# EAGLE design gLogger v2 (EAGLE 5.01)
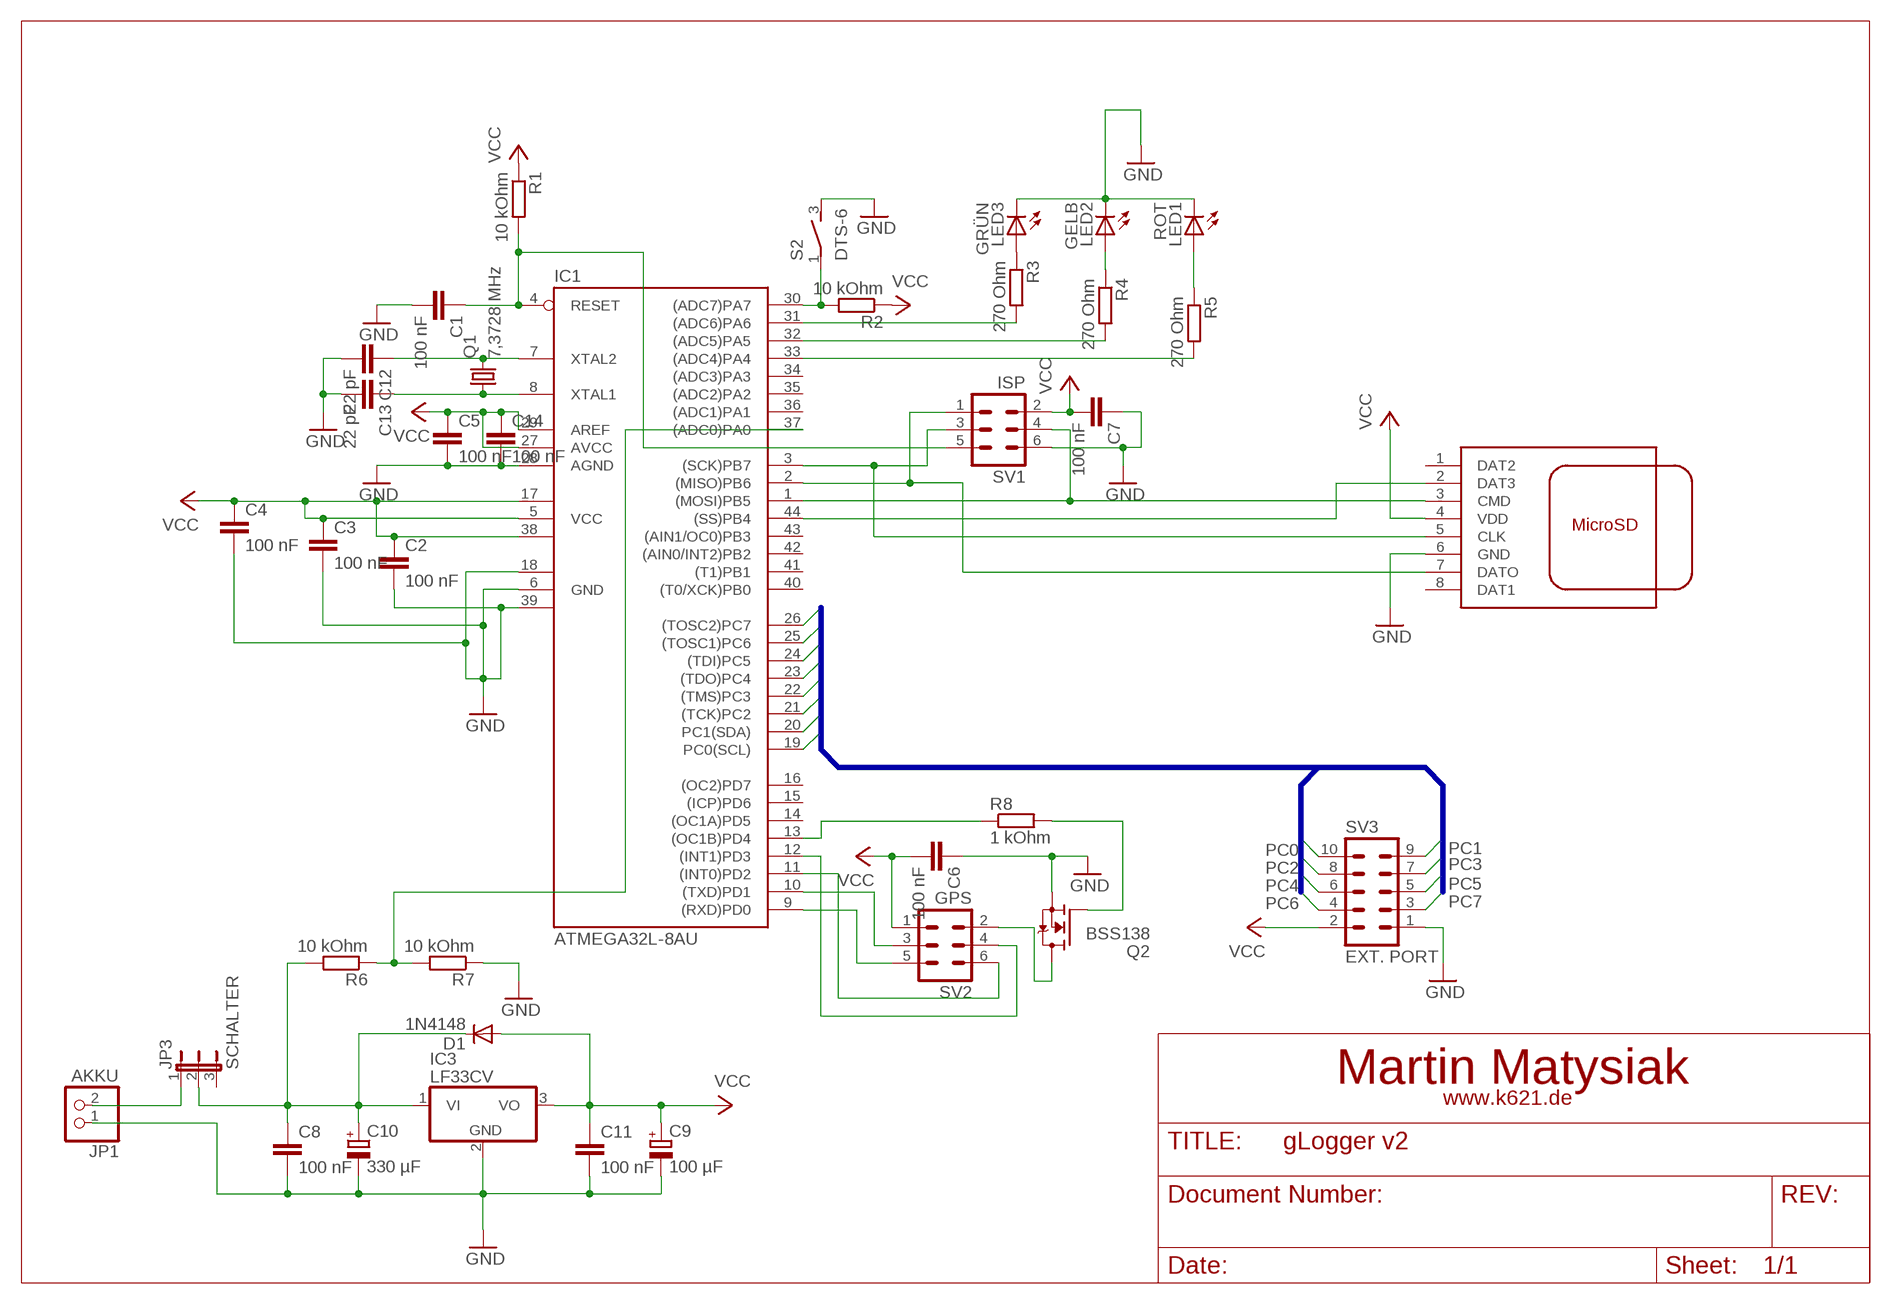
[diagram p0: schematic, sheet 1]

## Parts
C1  100 nF  C-EUC1206  [C1206]
C2  100 nF  C-EUC1206  [C1206]
C3  100 nF  C-EUC1206  [C1206]
C4  100 nF  C-EUC1206  [C1206]
C5  100 nF  C-EUC1206  [C1206]
C6  100 nF  C-EUC1206  [C1206]
C7  100 nF  C-EUC1206  [C1206]
C8  100 nF  C-EUC1206  [C1206]
C9  100 µF  CPOL-EUE2-5  [E2-5]
C10  330 µF  CPOL-EUE2-5  [E2-5]
C11  100 nF  C-EUC1206  [C1206]
C12  22 pF  C-EUC1206  [C1206]
C13  22 pF  C-EUC1206  [C1206]
C14  100 nF  C-EUC1206  [C1206]
D1  1N4148  [DO35-10]
IC1  ATMEGA32L-8AU  MEGA32-A  [TQFP44]
IC2  SCHA2B300  [SCHA2B300]
IC3  LF33CV  [TO220H]
JP1  AKKU  PINHD-1X2  [1X02]
JP3  SCHALTER  JP2E  [JP2]
LED1  ROT  LED3MM  [LED3MM]
LED2  GELB  LED3MM  [LED3MM]
LED3  GRÜN  LED3MM  [LED3MM]
Q1  7,3728 MHz  CRYSTALSM49  [SM49]
Q2  BSS138  [SOT23]
R1  10 kOhm  R-EU_R1206  [R1206]
R2  10 kOhm  R-EU_R1206  [R1206]
R3  270 Ohm  R-EU_R1206  [R1206]
R4  270 Ohm  R-EU_R1206  [R1206]
R5  270 Ohm  R-EU_R1206  [R1206]
R6  10 kOhm  R-EU_R1206  [R1206]
R7  10 kOhm  R-EU_R1206  [R1206]
R8  1 kOhm  R-EU_0207/5V  [0207/5V]
S2  DTS-6  [DTS-6]
SV1  ISP  MA03-2  [MA03-2]
SV2  GPS  MA03-2  [MA03-2]
SV3  EXT. PORT  MA05-2  [MA05-2]

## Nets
GND: C1.2 C2.2 C3.2 C4.2 C5.2 C6.1 C7.1 C8.2 C9.- C10.- C11.2 C12.2 C13.2 C14.2 IC1.6(GND) IC1.18(GND1) IC1.28(AGND) IC1.39(GND2) IC2.6(GND) IC3.2(GND) JP1.1 LED1.K(C) LED2.K(C) LED3.K(C) Q2.2(S) R7.1 S2.3(S) SV1.6 SV3.1
N$1: C1.1 IC1.4(RESET) R1.2 SV1.5
N$2: IC1.3((SCK)PB7) IC2.5(CLK) SV1.3
N$3: IC1.11((INT0)PD2) SV2.6
N$4: IC1.12((INT1)PD3) SV2.4
N$5: C13.1 IC1.8(XTAL1) Q1.1
N$6: LED1.A R5.1
N$7: LED2.A R4.1
N$8: LED3.A R3.1
N$9: IC1.30((ADC7)PA7) R2.2 S2.1(P)
N$10: IC1.31((ADC6)PA6) R3.2
N$11: IC1.32((ADC5)PA5) R4.2
N$12: IC1.33((ADC4)PA4) R5.2
N$14: JP1.2 JP3.1
N$15: C12.1 IC1.7(XTAL2) Q1.2
N$16: Q2.3(D) SV2.2
N$17: Q2.1(G) R8.2
N$18: C8.1 C10.+ D1.C IC3.1(VI) JP3.2 R6.2
N$19: IC1.37((ADC0)PA0) R6.1 R7.2
N$20: IC1.13((OC1B)PD4) R8.1
N$23: IC1.9((RXD)PD0) SV2.5
N$24: IC1.10((TXD)PD1) SV2.3
N$25: IC1.2((MISO)PB6) IC2.7(DATO) SV1.1
N$27: IC1.1((MOSI)PB5) IC2.3(CMD) SV1.4
N$30: IC1.44((SS)PB4) IC2.2(DAT3)
PC0: IC1.19(PC0(SCL)) SV3.10
PC1: IC1.20(PC1(SDA)) SV3.9
PC2: IC1.21((TCK)PC2) SV3.8
PC3: IC1.22((TMS)PC3) SV3.7
PC4: IC1.23((TDO)PC4) SV3.6
PC5: IC1.24((TDI)PC5) SV3.5
PC6: IC1.25((TOSC1)PC6) SV3.4
PC7: IC1.26((TOSC2)PC7) SV3.3
VCC: C2.1 C3.1 C4.1 C5.1 C6.2 C7.2 C9.+ C11.1 C14.1 D1.A IC1.5(VCC) IC1.17(VCC1) IC1.27(AVCC) IC1.29(AREF) IC1.38(VCC2) IC2.4(VDD) IC3.3(VO) R1.1 R2.1 SV1.2 SV2.1 SV3.2
Unconnected: IC1.14((OC1A)PD5) IC1.15((ICP)PD6) IC1.16((OC2)PD7) IC1.34((ADC3)PA3) IC1.35((ADC2)PA2) IC1.36((ADC1)PA1) IC1.40((T0/XCK)PB0) IC1.41((T1)PB1) IC1.42((AIN0/INT2)PB2) IC1.43((AIN1/OC0)PB3) IC2.1(DAT2) IC2.8(DAT1) JP3.3

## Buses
EXT.PORT:PC0,PC1,PC2,PC3,PC4,PC5,PC6,PC7

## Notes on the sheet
- Martin Matysiak
- www.k621.de

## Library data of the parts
C1-C8 C11-C14 = rcl:C-EU: CAPACITOR, European symbol
C9 C10 = rcl:CPOL-EU: POLARIZED CAPACITOR, European symbol
D1 = diode:1N4148: DIODE
IC1 = atmel:MEGA32: MICROCONTROLLER 32 Kbytes FLASH 2 Kbytes SRAM 1 Kbytes EEPROM USART 8-channel 10 bit ADC Source: www.atmel.com .. doc2503.pdf
IC2 = selfmade:SCHA2B300: SCHA2B300 Micro SD Slot Available at csd-electronics
IC3 = linear:LF33CV
JP1 = pinhead:PINHD-1X2: PIN HEADER
JP3 = jumper:JP2E: JUMPER
LED1-LED3 = led:LED: LED
Q1 = crystal:CRYSTAL: CRYSTAL
Q2 = transistor-fet:BSS138
R1-R8 = rcl:R-EU_: RESISTOR, European symbol
S2 = switch:DTS-6: DTS-6
SV1 SV2 = con-lstb:MA03-2: PIN HEADER
SV3 = con-lstb:MA05-2: PIN HEADER

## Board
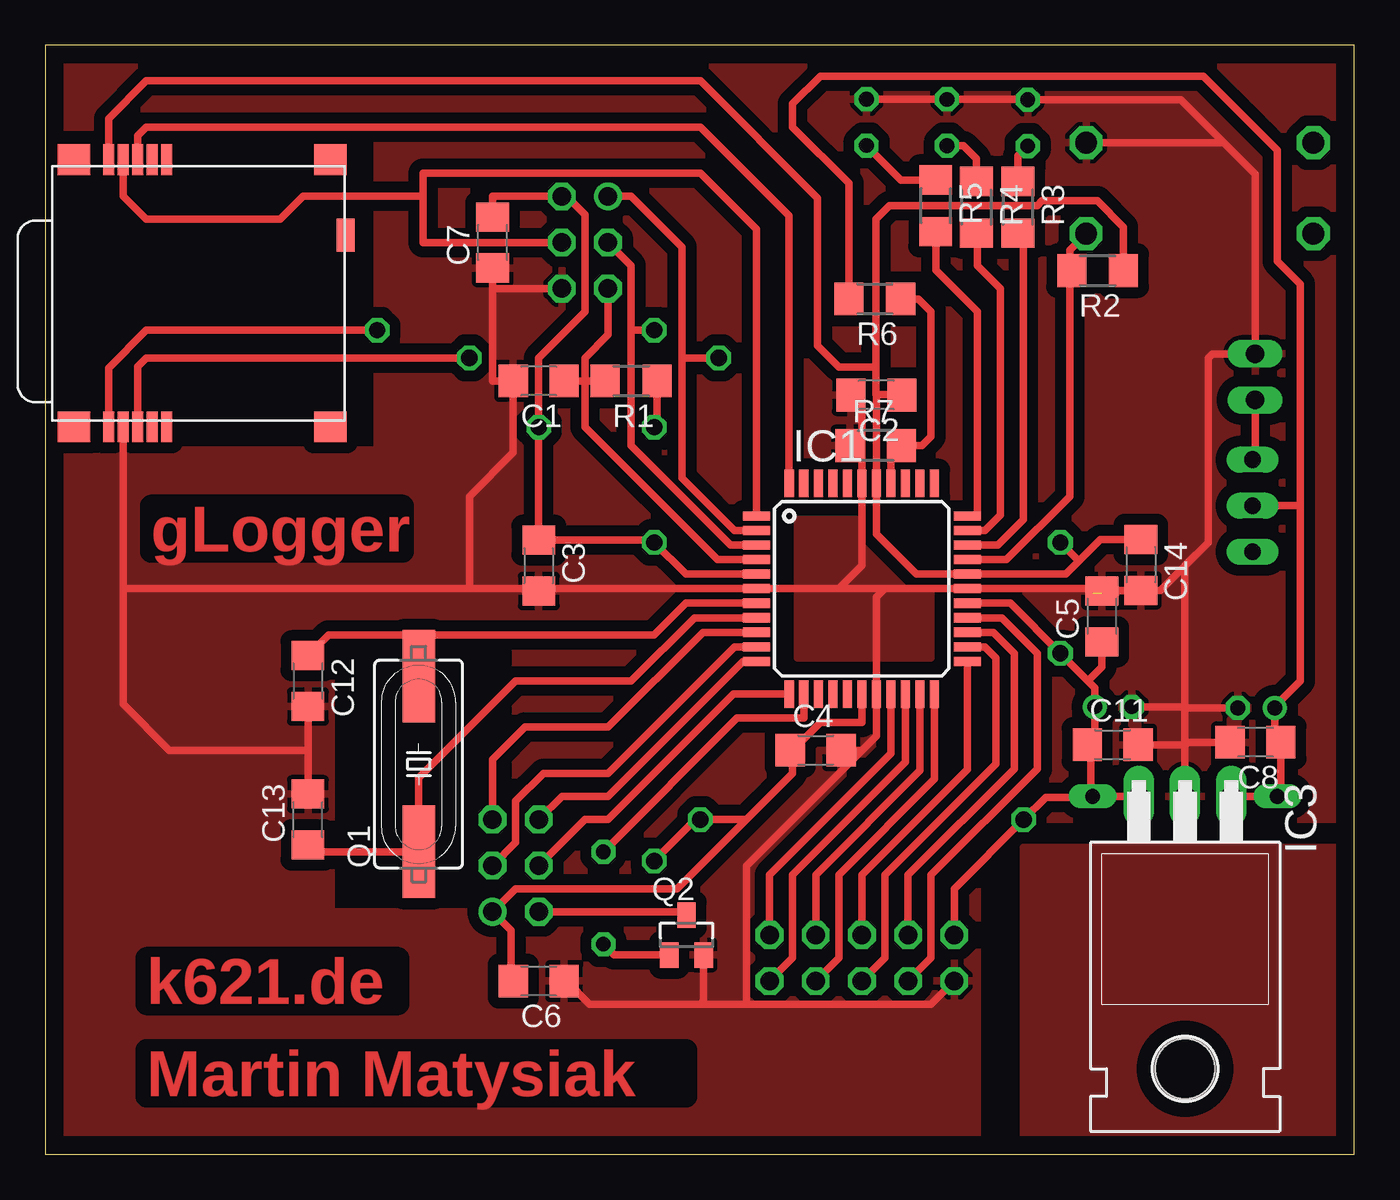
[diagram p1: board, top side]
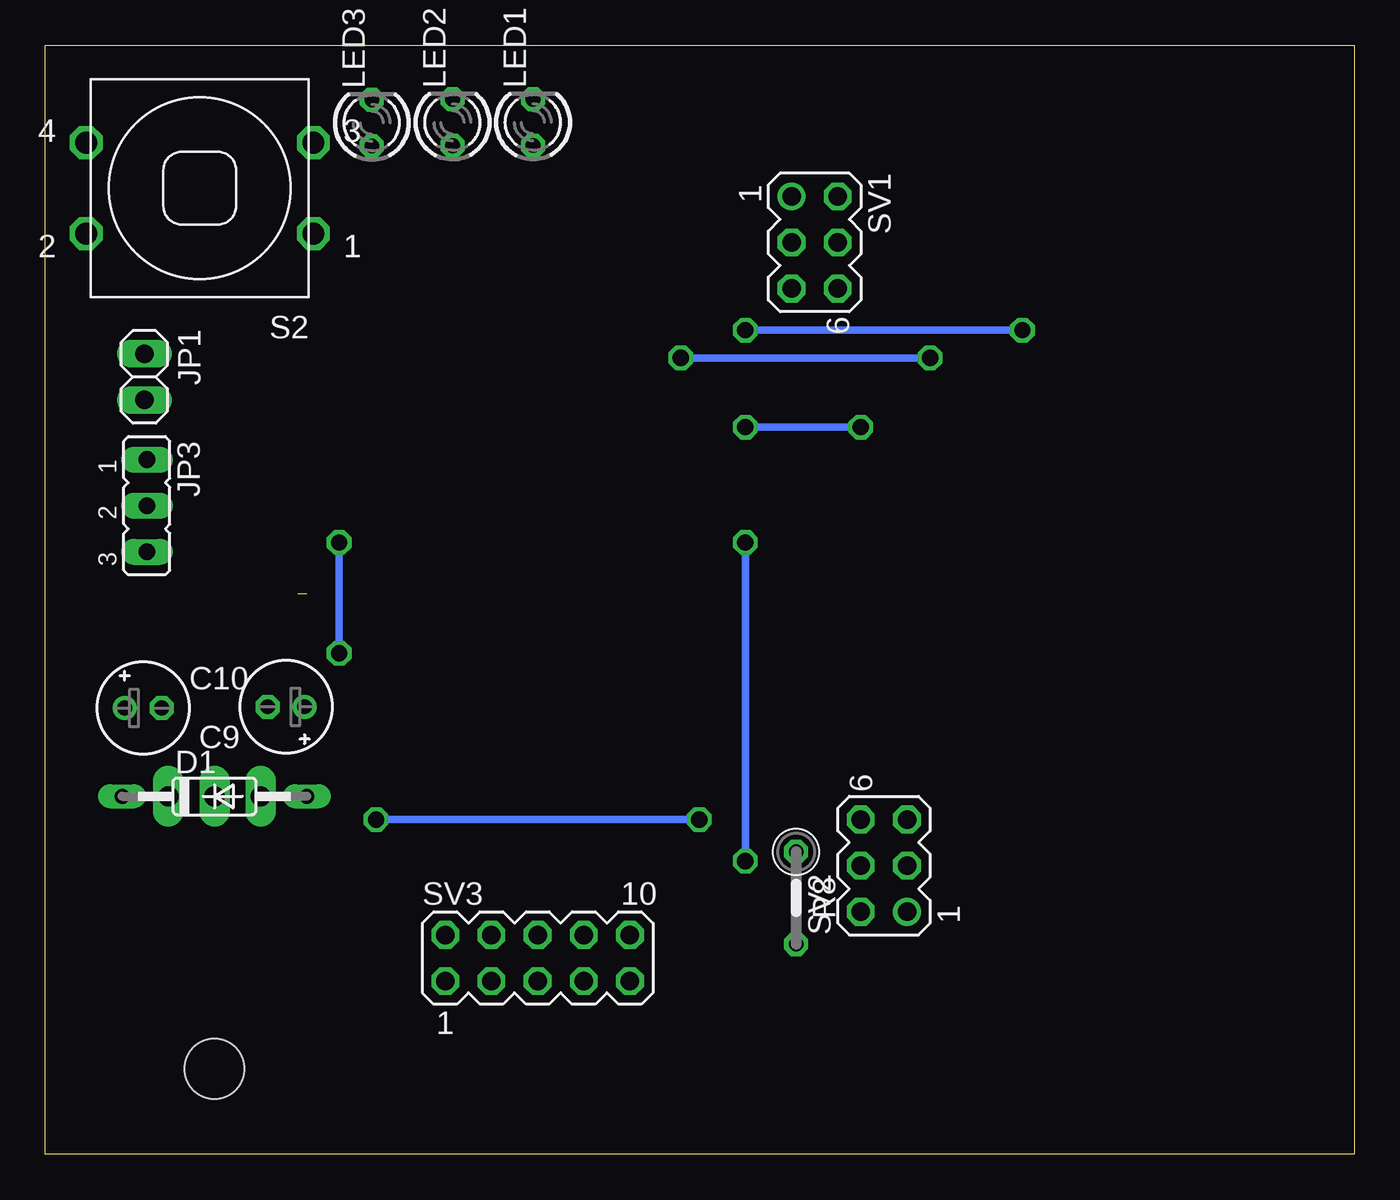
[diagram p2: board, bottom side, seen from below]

Size 72 x 61 mm. Coordinates in mm from the lower left corner, seen from the top.
Outline: 0,0 72,0 72,61 0,61 0,0
Copper layers (1*16): Top 0.035mm / dielectric 1.5mm / Bottom 0.035mm
Design rules "default *": minimum track width 10mil, minimum drill 24mil, track to track 0.2mm, track to pad 0.2mm, pad to pad 0.2mm, via to via 0.2mm, smd to smd 8mil, copper to edge 1mm, drill to drill 8mil, minimum pad ring 10mil, minimum via ring 8mil, stop-mask expansion 4mil, vias tented up to drill 0mil, thermal gap 10mil

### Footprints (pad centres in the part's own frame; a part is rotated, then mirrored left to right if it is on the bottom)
C1206 = smd 1.6 x 1.8: 1 -1.4,0; 2 1.4,0
E2-5 = drill 0.813 pad 1.27 round: + -1.016,0 | drill 0.813 pad 1.27 octagon: - 1.016,0
DO35-10 = drill 0.813 long: A 5.08,0; C -5.08,0
TQFP44 = smd 1.5 x 0.5: 1 -5.8,4; 2 -5.8,3.2; 3 -5.8,2.4; 4 -5.8,1.6; 5 -5.8,0.8; 6 -5.8,0; 7 -5.8,-0.8; 8 -5.8,-1.6; 9 -5.8,-2.4; 10 -5.8,-3.2; 11 -5.8,-4; 23 5.8,-4; 24 5.8,-3.2; 25 5.8,-2.4; 26 5.8,-1.6; 27 5.8,-0.8; 28 5.8,0; 29 5.8,0.8; 30 5.8,1.6; 31 5.8,2.4; 32 5.8,3.2; 33 5.8,4 | smd 0.5 x 1.5: 12 -4,-5.8; 13 -3.2,-5.8; 14 -2.4,-5.8; 15 -1.6,-5.8; 16 -0.8,-5.8; 17 0,-5.8; 18 0.8,-5.8; 19 1.6,-5.8; 20 2.4,-5.8; 21 3.2,-5.8; 22 4,-5.8; 34 4,5.8; 35 3.2,5.8; 36 2.4,5.8; 37 1.6,5.8; 38 0.8,5.8; 39 0,5.8; 40 -0.8,5.8; 41 -1.6,5.8; 42 -2.4,5.8; 43 -3.2,5.8; 44 -4,5.8
SCHA2B300 = smd 1.7 x 0.6: 1 -7.35,-9.8; 2 -7.35,-11.4; 3 -7.35,-12.2; 4 -7.35,-13; 5 7.35,-13; 6 7.35,-12.2; 7 7.35,-11.4; 8 7.35,-9.8; DUMMY -7.35,-10.6; DUMMY@2 7.35,-10.6 | smd 1.7 x 1.8: CARDDETECT 7.35,-0.8; N.C. -7.35,-0.8; N.C.@2 -7.35,-14.9; N.C.@3 7.35,-14.9 | smd 1.8 x 1: COMMON -3.2,0.05
TO220H = drill 1.118 long: 1 -2.54,-10.16; 2 0,-10.16; 3 2.54,-10.16 | hole 3.302: 0,4.826
1X02 = drill 1.016 long: 1 -1.27,0; 2 1.27,0
JP2 = drill 0.914 long: 1 -2.54,0; 2 0,0; 3 2.54,0
LED3MM = drill 0.813 octagon: A -1.27,0; K 1.27,0
SM49 = smd 5.08 x 1.778: 1 -4.826,0; 2 4.826,0
SOT23 = smd 1 x 1.4: 1 -0.95,-1.1; 2 0.95,-1.1; 3 0,1.1
R1206 = smd 1.6 x 1.803: 1 -1.422,0; 2 1.422,0
0207/5V = drill 0.813 octagon: 1 -2.54,0; 2 2.54,0
DTS-6 = drill 1.2 octagon: 1 -6.25,2.5; 2 6.25,2.5; 3 -6.25,-2.5; 4 6.25,-2.5
MA03-2 = drill 1.016 round: 1 -2.54,-1.27 | drill 1.016 octagon: 2 -2.54,1.27; 3 0,-1.27; 4 0,1.27; 5 2.54,-1.27; 6 2.54,1.27
MA05-2 = drill 1.016 octagon: 1 -5.08,-1.27; 2 -5.08,1.27; 3 -2.54,-1.27; 4 -2.54,1.27; 5 0,-1.27; 6 0,1.27; 7 2.54,-1.27; 8 2.54,1.27; 9 5.08,-1.27; 10 5.08,1.27

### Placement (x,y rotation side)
C1  27.14,42.54 180 top
C2  45.72,41.77 180 top
C3  27.14,32.38 270 top
C4  42.38,22.22 0 top
C5  58.13,29.59 90 top
C6  27.14,9.52 180 top
C7  24.6,50.16 90 top
C8  66.58,22.66 180 top
C9  58.76,24.61 180 bottom
C10  66.63,24.54 0 bottom
C11  58.72,22.52 0 top
C12  14.44,26.03 270 top
C13  14.44,18.41 90 top
C14  60.27,32.42 270 top
D1  62.7,19.68 0 bottom
IC1  44.92,31.11 0 top
IC2  16.47,47.37 270 top
IC3  62.7,9.52 180 top
JP1  66.56,42.76 270 bottom
JP3  66.42,35.67 270 bottom
LED1  45.17,56.76 90 bottom
LED2  49.6,56.76 90 bottom
LED3  54.04,56.74 90 bottom
Q1  20.54,21.46 90 top
Q2  35.27,12.06 0 top
R1  32.22,42.54 180 top
R2  57.89,48.61 180 top
R3  53.51,52.1 270 top
R4  51.22,52.1 270 top
R5  48.98,52.18 270 top
R6  45.63,47.05 180 top
R7  45.68,38.98 0 top
R8  30.7,14.09 270 bottom
S2  63.51,53.15 180 bottom
SV1  29.68,50.16 270 bottom
SV2  25.87,15.87 90 bottom
SV3  44.92,10.79 0 bottom

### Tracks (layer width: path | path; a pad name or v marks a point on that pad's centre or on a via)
GND  (1 unrouted)
  Top 0.406: 44.92,22.22 45.72,23.02 IC1.18 45.72,30.64 46.19,31.11 | 44.92,38.98 IC1.39 44.92,32.38 43.65,31.11 | 46.19,31.11 IC1.28 58.89,31.11 58.89,31.02 | 43.65,31.11 46.19,31.11 | 43.65,31.11 IC1.6 27.14,31.11 | 44.92,22.22 C4.2 | 44.92,22.22 38.57,15.87 38.57,8.25 | 38.57,8.25 48.73,8.25 SV3.1 | 28.66,9.52 29.93,8.25 36.03,8.25 | 38.57,8.25 36.03,8.25 | 44.92,38.98 R7.1 | 4.27,31.11 4.27,24.77 6.82,22.22 14.44,22.22 | 4.27,31.11 IC2.6 | 14.44,22.22 C13.2 | 14.44,22.22 C12.2 | 24.6,47.62 SV1.6 | 24.6,47.62 C7.1 | 24.6,47.62 24.6,42.54 C1.2 25.74,38.6 23.33,36.19 23.33,31.11 | 27.14,31.11 C3.2 | 4.27,31.11 23.33,31.11 | 23.33,31.11 27.14,31.11 | 62.7,22.47 IC3.2 | 62.7,24.51 62.7,22.47 | 62.7,24.76 62.7,24.51 | C11.2 62.65,22.52 62.7,22.47 | C8.2 62.88,22.66 62.7,22.47 | C10.- 62.74,24.54 62.7,24.51 | 62.7,24.76 62.55,24.61 C9.- 62.7,24.61 62.7,24.76 | C2.2 44.92,41.78 44.92,38.98 | 57.46,31.02 57.62,30.86 | 63.97,33.65 63.97,43.81 64.19,44.03 JP1.1 66.56,53.92 66.51,53.97 | 62.7,24.76 62.7,32.38 63.97,33.65 | 58.13,31.11 C5.2 58.13,30.86 | 58.13,30.86 58.29,31.02 | S2.3 64.83,55.65 66.51,53.97 | LED1.K 49.49,58.03 49.5,58.03 LED2.K 54.06,58.03 | 54.06,58.03 LED3.K 62.47,58.01 66.51,53.97 | 54.06,58.03 | 58.89,31.02 58.89,30.86 58.13,30.86 | 58.89,31.02 C14.2 61.34,31.02 63.97,33.65 | Q2.2 36.22,8.44 36.03,8.25
  pour Top (isolate 0.61): 71.59,18.41 71.59,61.59 0.47,61.59 0.47,56.51 18.25,56.51 18.25,36.19 51.27,36.19 51.27,18.41
  pour Top (isolate 0.61): 51.27,0.63 51.27,26.03 38.57,26.03 38.57,36.19 25.87,36.19 25.87,0.63
  pour Top (isolate 0.61): 0.47,38.73 25.87,38.73 25.87,28.57 15.71,28.57 15.71,0.63 0.47,0.63
  pour Top (isolate 0.61): 25.87,0.63 15.71,0.63 15.71,13.33 25.87,13.33
  pour Top (isolate 0.61): 48.73,31.11 48.73,34.92 41.36,34.92 41.36,27.3 48.73,27.3
N$1
  Top 0.406: IC1.4 36.97,32.71 29.68,40 29.68,42.54 | 29.68,42.54 C1.1 | 29.68,42.54 R1.2 | 29.68,42.54 29.68,43.81 30.95,45.08 SV1.5
N$2  (via drill 0.9 pad 1.02)
  Top 0.406: IC2.5 3.47,43.26 5.55,45.33 v18.25,45.33 | SV1.3 32.22,48.89 32.22,45.33 | 32.22,45.33 32.22,38.98 37.69,33.51 IC1.3 | v33.49,45.33 32.22,45.33
  Bottom 0.406: v18.25,45.33 v33.49,45.33
N$3
  Top 0.406: IC1.11 38.38,27.11 30.95,19.68 28.41,19.68 SV2.6
N$4
  Top 0.406: IC1.12 37.85,25.31 30.95,18.41 29.68,18.41 SV2.4
N$5
  Top 0.406: IC1.8 35.7,29.51 32.22,26.03 25.87,26.03 20.54,20.7 Q1.1 14.82,16.63 C13.1
N$6
  Top 0.406: R5.1 47.07,53.6 LED1.A
N$7
  Top 0.406: R4.1 51.22,54.78 50.51,55.49 49.49,55.49 49.5,55.49 LED2.A
N$8
  Top 0.406: LED3.A 54.06,55.49 | LED3.A | R3.1 53.51,54.94 LED3.A
N$9
  Top 0.406: IC1.30 52.87,32.71 56.35,36.19 56.35,48.64 | 56.35,48.64 56.38,48.61 R2.2 | R2.2 56.58,48.61 56.6,48.64 55.99,49.25 | 56.35,48.64 56.44,48.64 R2.2 | S2.1 56.35,49.74 56.35,48.64
N$10
  Top 0.406: IC1.31 52.4,33.51 53.81,34.92 53.81,50.16 53.51,50.46 R3.2
N$11
  Top 0.406: IC1.32 51.68,34.31 52.54,35.17 52.54,47.62 51.27,48.89 51.27,50.41 51.22,50.46 R4.2
N$12
  Top 0.406: R5.2 48.98,48.64 51.27,46.35 51.27,35.11 IC1.33
N$13
  pour Top (isolate 0.406): 53.81,16.89 71.59,16.89 71.59,0.63 53.81,0.63
N$14
  Top 0.406: JP3.1 66.5,38.21 66.56,38.27 JP1.2
N$15
  Top 0.406: IC1.7 35.23,30.31 33.49,28.57 20.79,28.57 | C12.1 15.58,28.57 20.79,28.57 | Q1.2 20.79,26.28 20.79,28.57
N$16
  Top 0.406: 35.27,13.08 Q2.3 35.27,13.33 SV2.2
N$17
  Top 0.406: Q2.1 31.29,10.96 R8.2
N$18
  Top 0.406: IC3.1 67.42,19.68 67.47,19.63 67.52,19.68 D1.C 67.98,19.88 C8.1 67.98,22.67 68.03,22.73 67.64,23.12 C10.+ 67.78,24.68 67.78,24.76 69.05,26.03 69.05,35.68 | R6.2 44.21,53.41 41.11,56.51 41.11,57.78 42.63,59.3 63.72,59.3 67.78,55.24 67.78,49.14 69.05,47.87 69.05,35.68 | JP3.2 66.43,35.68 69.05,35.68
N$19
  Top 0.406: IC1.37 46.52,38.55 46.95,38.98 | 46.95,38.98 R7.2 | 46.95,38.98 48.22,38.98 48.73,39.49 48.73,46.35 48.03,47.05 R6.1
N$20
  Top 0.406: IC1.13 41.72,24 38.06,24 R8.1
N$23
  Top 0.406: IC1.9 36.17,28.71 30.95,23.49 26.38,23.49 24.6,21.71 24.6,18.66 24.85,18.41 SV2.5
N$24
  Top 0.406: IC1.10 37.91,27.91 30.95,20.95 27.39,20.95 25.87,19.43 25.87,17.14 SV2.3
N$25  (via drill 0.9 pad 1.02)
  Top 0.406: IC2.7 5.07,43.33 5.55,43.81 v23.33,43.81 | IC1.2 37.91,34.31 35.01,37.21 35.01,43.81 | SV1.1 32.22,52.7 35.01,49.91 35.01,43.81 | v37.05,43.81 35.01,43.81
  Bottom 0.406: v23.33,43.81 v37.05,43.81
N$27
  Top 0.406: IC1.1 39.12,50.88 36.03,53.97 20.79,53.97 20.79,52.7 | 20.79,52.7 20.79,50.16 SV1.4 | IC2.3 4.27,52.71 5.55,51.43 12.92,51.43 14.19,52.7 20.79,52.7
N$30
  Top 0.406: IC2.2 5.07,56.03 5.55,56.51 36.03,56.51 40.92,51.62 IC1.44
PC0
  Top 0.406: IC1.19 46.52,22.04 39.84,15.36 SV3.10
PC1
  Top 0.406: IC1.20 47.32,21.57 41.11,15.36 41.11,10.79 SV3.9
PC2
  Top 0.406: IC1.21 48.12,21.1 42.38,15.36 SV3.8
PC3
  Top 0.406: IC1.22 48.92,20.63 43.65,15.36 43.65,10.79 SV3.7
PC4
  Top 0.406: IC1.23 50.72,21.16 44.92,15.36 SV3.6
PC5
  Top 0.406: IC1.24 51.68,27.91 52.29,27.3 52.29,21.46 46.19,15.36 46.19,10.79 SV3.5
PC6
  Top 0.406: IC1.25 52.15,28.71 53.3,27.55 53.3,21.2 47.46,15.36 SV3.4
PC7
  Top 0.406: IC1.26 52.62,29.51 54.57,27.55 54.57,21.2 48.73,15.36 48.73,10.79 SV3.3
VCC  (via drill 0.9 pad 1.02)
  Top 0.406: 38.57,18.41 34.76,14.6 25.87,14.6 SV2.1 25.62,12.31 25.62,9.52 C6.2 | 38.57,18.41 41.11,20.95 41.11,22.22 | IC1.17 44.92,23.74 42.63,23.74 41.11,22.22 | 40.98,22.09 40.86,21.97 | 40.98,22.09 C4.1 41.11,22.22 | 41.11,22.22 40.98,22.09 | C7.2 24.6,52.7 SV1.2 28.66,52.7 29.68,51.68 29.68,46.35 27.14,43.81 v27.14,40 C3.1 33.36,33.78 v33.49,33.65 35.23,31.91 IC1.5 | IC2.4 3.47,56.97 5.55,59.05 36.03,59.05 42.47,52.61 42.47,44.48 43.65,43.3 45.68,43.3 | R1.1 33.64,40.15 v33.49,40 | 57.52,19.68 D1.A IC3.3 | 57.52,19.68 57.47,19.63 55.03,19.63 v53.81,18.41 50,14.6 SV3.2 | 57.52,19.68 57.52,22.32 C11.1 57.57,22.52 57.62,22.47 57.74,22.6 C9.+ 57.74,25.65 57.37,26.03 | 38.57,18.41 v36.03,18.41 35.78,18.41 v33.49,16.12 | 57.37,26.03 v55.84,27.55 53.09,30.31 IC1.27 | C2.1 45.72,41.78 | 45.72,41.78 IC1.38 45.72,34.12 47.93,31.91 IC1.29 56.13,31.91 56.86,32.63 | 45.72,41.78 45.68,41.78 45.68,43.3 | C5.1 58.13,26.79 57.37,26.03 | C14.1 58.04,33.82 56.86,32.63 | R2.1 59.31,51.01 57.87,52.45 54.83,52.45 54.57,52.19 46.44,52.19 45.68,51.43 45.68,43.3 | v55.84,33.65 56.86,32.63
  Bottom 0.406: v27.14,40 v33.49,40 | v36.03,18.41 v53.81,18.41 | v33.49,16.12 v33.49,33.65 | v55.84,27.55 v55.84,33.65

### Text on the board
Top: gLogger | k621.de | Martin Matysiak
